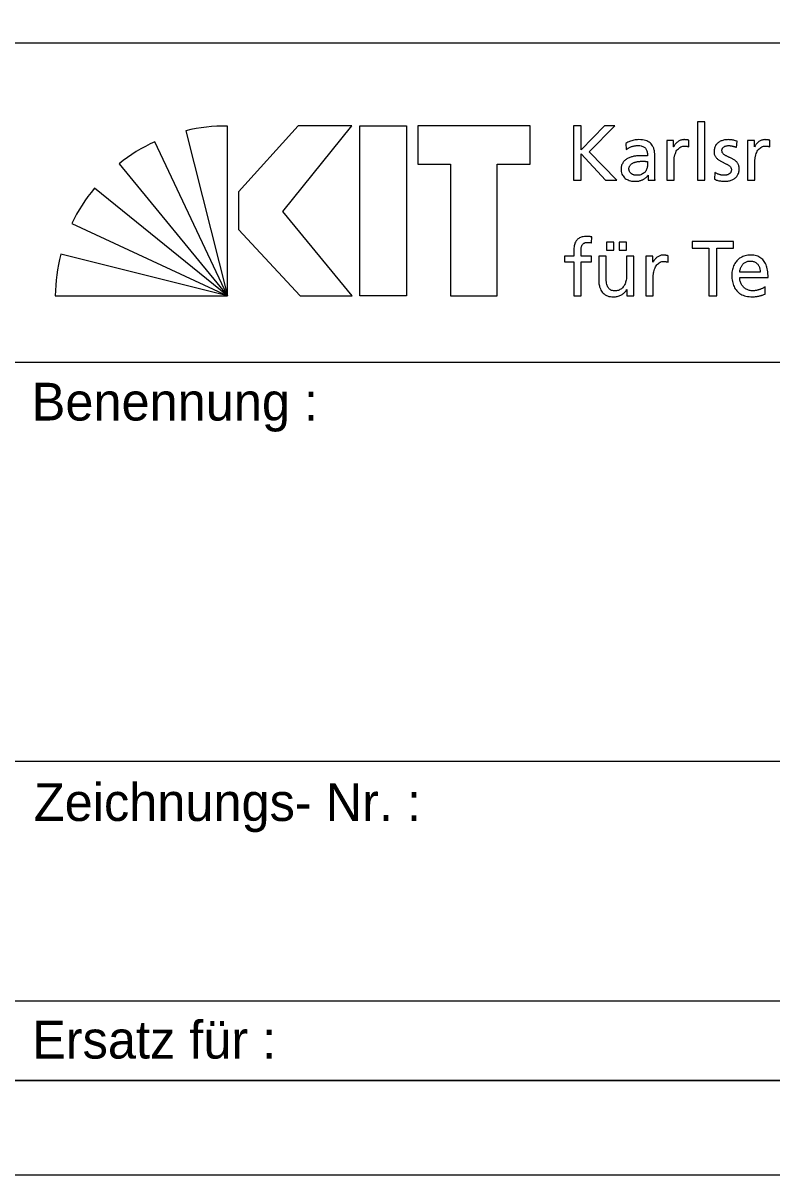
# Model space of a CAD drawing. Extents: x 0 to 297, y 0 to 210.
# Drawn here: x 252.83 to 272.66, y 0 to 30.52 of the extents above; entities that cross this region are included whole.
import ezdxf

# ---------------------------------------------------------------- set-up
doc = ezdxf.new("R2010")
doc.units = 0
doc.layers.add('90_Plankopf', color=7, linetype='Continuous')

msp = doc.modelspace()

# ---------------------------------------------------------------- linework, layer by layer
at = {"layer": '90_Plankopf'}
for p, q in [((205.56, 29.995), (294.5, 29.995)), ((205.56, 29.995), (294.5, 29.995)), ((258.24, 23.293), (258.24, 27.792)), ((267.405, 27.793), (267.405, 26.353)), ((257.137, 27.666), (258.24, 23.293)), ((258.24, 23.293), (256.317, 27.376)), ((268.79, 27.331), (268.8, 27.166)), ((270.463, 27.242), (270.463, 27.416)), ((271.728, 27.22), (271.745, 27.389)), ((272.606, 27.242), (272.606, 27.416)), ((269.559, 26.559), (269.559, 26.995)), ((255.372, 26.793), (258.24, 23.293)), ((269.365, 26.854), (269.365, 26.761)), ((271.149, 26.559), (271.138, 26.386)), ((267.405, 26.353), (267.611, 26.353)), ((268.253, 26.353), (268.554, 26.353)), ((258.24, 23.293), (254.717, 26.143)), ((254.12, 25.207), (258.24, 23.293)), ((267.887, 24.696), (267.895, 24.853)), ((258.24, 23.293), (253.829, 24.394)), ((269.913, 24.182), (269.913, 24.356)), ((272.353, 23.92), (271.808, 23.92)), ((271.808, 23.776), (272.559, 23.776)), ((272.479, 23.337), (272.479, 23.53)), ((253.682, 23.293), (258.24, 23.293)), ((252.501, 21.535), (294.5, 21.535)), ((252.501, 10.96), (294.5, 10.96)), ((252.501, 4.615), (294.5, 4.615)), ((294.5, 2.5), (205.56, 2.5)), ((211.4, 2.5), (294.5, 2.5)), ((211.4, 2.5), (294.5, 2.5))]:
    msp.add_line(p, q, dxfattribs=at)
for points in [[(0, 0), (297, 0), (297, 210), (0, 210)], [(12.5, 207.5), (294.5, 207.5), (294.5, 2.5), (12.5, 2.5)], [(261.533, 27.793), (260.118, 27.793), (258.536, 26.049), (258.536, 25.046), (260.169, 23.293), (261.542, 23.293), (259.711, 25.531)], [(262.985, 27.793), (262.985, 23.293), (261.751, 23.293), (261.751, 27.793)], [(263.281, 27.793), (263.281, 26.78), (264.151, 26.78), (264.151, 23.293), (265.385, 23.293), (265.385, 26.78), (266.255, 26.78), (266.255, 27.793)]]:
    msp.add_lwpolyline(points, close=True, dxfattribs=at)
for points in [[(268.554, 26.353), (267.824, 27.112), (268.5, 27.793), (268.226, 27.793), (267.611, 27.16), (267.611, 27.793), (267.405, 27.793)], [(270.69, 26.353), (270.884, 26.353), (270.884, 27.9), (270.69, 27.9), (270.69, 26.353)], [(270.061, 27.242), (270.057, 27.242), (270.057, 27.405), (269.875, 27.405), (269.875, 26.353), (270.069, 26.353), (270.069, 26.832)], [(272.203, 27.242), (272.199, 27.242), (272.199, 27.405), (272.018, 27.405), (272.018, 26.353), (272.212, 26.353), (272.212, 26.832)], [(267.611, 26.353), (267.611, 27.059), (268.253, 26.353)], [(269.382, 26.489), (269.386, 26.489), (269.386, 26.353), (269.567, 26.353)], [(270.995, 23.293), (271.201, 23.293), (271.201, 24.552), (271.649, 24.552), (271.649, 24.733), (270.547, 24.733), (270.547, 24.552), (270.995, 24.552), (270.995, 23.293)], [(267.412, 24.443), (267.412, 24.346), (267.165, 24.346), (267.165, 24.189), (267.412, 24.189), (267.412, 23.293), (267.606, 23.293), (267.606, 24.189), (267.885, 24.189), (267.885, 24.346), (267.606, 24.346), (267.606, 24.459)], [(268.277, 24.713), (268.277, 24.506), (268.471, 24.506), (268.471, 24.713), (268.277, 24.713)], [(268.615, 24.713), (268.615, 24.506), (268.809, 24.506), (268.809, 24.713), (268.615, 24.713)], [(268.271, 23.801), (268.271, 24.346), (268.077, 24.346), (268.077, 23.72)], [(269.007, 23.293), (269.007, 24.346), (268.813, 24.346), (268.813, 23.859)], [(269.511, 24.182), (269.507, 24.182), (269.507, 24.346), (269.325, 24.346), (269.325, 23.293), (269.519, 23.293), (269.519, 23.772)], [(268.816, 23.46), (268.82, 23.46), (268.82, 23.293), (269.007, 23.293)]]:
    msp.add_lwpolyline(points, dxfattribs=at)
for centre, start, end in [((258.224, 23.028), 89.8053, 103.1895), ((258.331, 23.059), 115.0126, 128.3968), ((258.408, 23.131), 140.7898, 154.174), ((258.446, 23.219), 165.7222, 179.1064)]:
    msp.add_arc(centre, 4.764, start, end, dxfattribs=at)
for points in [[(269.559, 26.995), (269.56, 27.09), (269.545, 27.17), (269.517, 27.235), (269.488, 27.3), (269.442, 27.348), (269.38, 27.381), (269.317, 27.413), (269.236, 27.43), (269.136, 27.43), (269.069, 27.43), (269.007, 27.42), (268.949, 27.402), (268.891, 27.384), (268.838, 27.361), (268.79, 27.331)], [(268.8, 27.166), (268.826, 27.188), (268.856, 27.207), (268.89, 27.223), (268.923, 27.239), (268.958, 27.251), (268.995, 27.26), (269.032, 27.269), (269.068, 27.273), (269.105, 27.273), (269.17, 27.273), (269.221, 27.263), (269.259, 27.243), (269.297, 27.222), (269.324, 27.191), (269.341, 27.151), (269.358, 27.11), (269.365, 27.059), (269.365, 26.999)], [(270.463, 27.416), (270.45, 27.418), (270.437, 27.421), (270.425, 27.423), (270.412, 27.425), (270.399, 27.427), (270.385, 27.428), (270.371, 27.429), (270.354, 27.43), (270.335, 27.43), (270.298, 27.43), (270.261, 27.422), (270.226, 27.406), (270.191, 27.39), (270.159, 27.368), (270.13, 27.339), (270.101, 27.311), (270.078, 27.279), (270.061, 27.242)], [(270.069, 26.832), (270.069, 26.92), (270.081, 26.996), (270.105, 27.06), (270.129, 27.124), (270.162, 27.174), (270.205, 27.208), (270.247, 27.243), (270.298, 27.26), (270.356, 27.261), (270.373, 27.261), (270.39, 27.26), (270.409, 27.257), (270.427, 27.254), (270.445, 27.249), (270.463, 27.242)], [(271.745, 27.389), (271.707, 27.4), (271.669, 27.41), (271.63, 27.418), (271.591, 27.426), (271.549, 27.43), (271.504, 27.43), (271.451, 27.43), (271.403, 27.423), (271.358, 27.41), (271.313, 27.397), (271.274, 27.377), (271.24, 27.35), (271.206, 27.323), (271.18, 27.29), (271.161, 27.249), (271.142, 27.208), (271.132, 27.161), (271.132, 27.106), (271.132, 27.064), (271.141, 27.028), (271.158, 26.997), (271.174, 26.966), (271.195, 26.94), (271.223, 26.917), (271.25, 26.895), (271.279, 26.875), (271.312, 26.857), (271.344, 26.84), (271.376, 26.824), (271.409, 26.809), (271.441, 26.793), (271.471, 26.777), (271.498, 26.761), (271.525, 26.745), (271.547, 26.727), (271.563, 26.706), (271.579, 26.686), (271.588, 26.663), (271.588, 26.636), (271.588, 26.607), (271.582, 26.584), (271.57, 26.564), (271.558, 26.545), (271.542, 26.529), (271.522, 26.518), (271.503, 26.506), (271.482, 26.498), (271.459, 26.493), (271.435, 26.487), (271.412, 26.485), (271.39, 26.485), (271.371, 26.485), (271.347, 26.488), (271.32, 26.493), (271.292, 26.499), (271.263, 26.507), (271.233, 26.518), (271.203, 26.529), (271.175, 26.543), (271.149, 26.559)], [(271.138, 26.386), (271.183, 26.363), (271.23, 26.347), (271.279, 26.339), (271.328, 26.331), (271.377, 26.327), (271.427, 26.328), (271.475, 26.328), (271.52, 26.335), (271.564, 26.348), (271.607, 26.361), (271.647, 26.381), (271.681, 26.408), (271.716, 26.435), (271.743, 26.469), (271.764, 26.51), (271.784, 26.551), (271.794, 26.6), (271.795, 26.656), (271.794, 26.704), (271.786, 26.745), (271.769, 26.778), (271.753, 26.811), (271.731, 26.84), (271.704, 26.863), (271.677, 26.886), (271.647, 26.906), (271.615, 26.922), (271.583, 26.939), (271.55, 26.954), (271.518, 26.968), (271.486, 26.983), (271.456, 26.998), (271.429, 27.013), (271.402, 27.029), (271.38, 27.047), (271.364, 27.068), (271.347, 27.089), (271.339, 27.115), (271.338, 27.145), (271.339, 27.174), (271.348, 27.198), (271.365, 27.217), (271.382, 27.236), (271.404, 27.25), (271.432, 27.259), (271.46, 27.269), (271.491, 27.273), (271.524, 27.273), (271.536, 27.273), (271.551, 27.271), (271.569, 27.269), (271.588, 27.266), (271.607, 27.261), (271.627, 27.256), (271.648, 27.251), (271.667, 27.246), (271.685, 27.239), (271.703, 27.233), (271.717, 27.226), (271.728, 27.22)], [(272.606, 27.416), (272.592, 27.418), (272.579, 27.421), (272.567, 27.423), (272.555, 27.425), (272.541, 27.427), (272.527, 27.428), (272.513, 27.429), (272.497, 27.43), (272.478, 27.43), (272.44, 27.43), (272.404, 27.422), (272.368, 27.406), (272.333, 27.39), (272.301, 27.368), (272.273, 27.339), (272.244, 27.311), (272.221, 27.279), (272.203, 27.242)], [(272.212, 26.832), (272.212, 26.92), (272.224, 26.996), (272.247, 27.06), (272.271, 27.124), (272.304, 27.174), (272.347, 27.208), (272.39, 27.243), (272.44, 27.26), (272.498, 27.261), (272.515, 27.261), (272.533, 27.26), (272.551, 27.257), (272.57, 27.254), (272.588, 27.249), (272.606, 27.242)], [(269.365, 26.999), (269.34, 27), (269.317, 27.001), (269.295, 27.001), (269.273, 27.002), (269.251, 27.003), (269.229, 27.003), (269.208, 27.003), (269.184, 27.003), (269.159, 27.003), (269.118, 27.003), (269.076, 26.999), (269.031, 26.992), (268.987, 26.985), (268.943, 26.973), (268.9, 26.957), (268.858, 26.941), (268.819, 26.919), (268.784, 26.892), (268.75, 26.866), (268.722, 26.833), (268.701, 26.794), (268.681, 26.755), (268.671, 26.709), (268.67, 26.656), (268.671, 26.58), (268.687, 26.518), (268.719, 26.469), (268.752, 26.421), (268.797, 26.385), (268.855, 26.362), (268.913, 26.339), (268.979, 26.328), (269.056, 26.328), (269.1, 26.328), (269.14, 26.334), (269.175, 26.344), (269.21, 26.355), (269.241, 26.368), (269.268, 26.384), (269.295, 26.401), (269.318, 26.419), (269.337, 26.437), (269.355, 26.455), (269.37, 26.472), (269.382, 26.489)], [(269.365, 26.761), (269.365, 26.709), (269.354, 26.661), (269.332, 26.62), (269.31, 26.578), (269.277, 26.546), (269.233, 26.522), (269.19, 26.498), (269.136, 26.485), (269.072, 26.485), (269.05, 26.485), (269.027, 26.489), (269.004, 26.496), (268.981, 26.503), (268.96, 26.514), (268.941, 26.529), (268.922, 26.543), (268.906, 26.561), (268.894, 26.582), (268.883, 26.604), (268.877, 26.628), (268.876, 26.656), (268.877, 26.693), (268.886, 26.724), (268.904, 26.749), (268.922, 26.773), (268.946, 26.793), (268.975, 26.807), (269.003, 26.822), (269.034, 26.833), (269.067, 26.841), (269.1, 26.848), (269.132, 26.853), (269.163, 26.855), (269.194, 26.858), (269.22, 26.859), (269.241, 26.858), (269.262, 26.858), (269.283, 26.858), (269.303, 26.856), (269.324, 26.855), (269.345, 26.855), (269.365, 26.854)], [(269.567, 26.353), (269.566, 26.363), (269.565, 26.377), (269.563, 26.393), (269.562, 26.411), (269.561, 26.433), (269.561, 26.46), (269.56, 26.486), (269.559, 26.52), (269.559, 26.559)], [(267.895, 24.853), (267.875, 24.856), (267.855, 24.859), (267.834, 24.862), (267.812, 24.864), (267.79, 24.866), (267.765, 24.866), (267.694, 24.865), (267.635, 24.855), (267.589, 24.836), (267.543, 24.816), (267.507, 24.787), (267.481, 24.75), (267.455, 24.713), (267.437, 24.668), (267.427, 24.616), (267.417, 24.565), (267.412, 24.507), (267.412, 24.443)], [(267.606, 24.459), (267.606, 24.495), (267.608, 24.528), (267.612, 24.558), (267.616, 24.588), (267.625, 24.615), (267.637, 24.637), (267.65, 24.66), (267.669, 24.677), (267.694, 24.69), (267.719, 24.702), (267.752, 24.709), (267.794, 24.709), (267.811, 24.709), (267.828, 24.708), (267.844, 24.706), (267.861, 24.703), (267.875, 24.7), (267.887, 24.696)], [(269.913, 24.356), (269.9, 24.359), (269.887, 24.361), (269.875, 24.363), (269.863, 24.365), (269.849, 24.367), (269.835, 24.368), (269.821, 24.37), (269.804, 24.37), (269.786, 24.37), (269.748, 24.37), (269.712, 24.362), (269.676, 24.346), (269.641, 24.33), (269.609, 24.308), (269.581, 24.28), (269.552, 24.252), (269.529, 24.219), (269.511, 24.182)], [(269.519, 23.772), (269.52, 23.86), (269.532, 23.937), (269.555, 24.001), (269.579, 24.065), (269.612, 24.114), (269.655, 24.148), (269.698, 24.183), (269.748, 24.201), (269.806, 24.201), (269.823, 24.201), (269.841, 24.2), (269.859, 24.197), (269.878, 24.195), (269.896, 24.19), (269.913, 24.182)], [(272.559, 23.776), (272.56, 23.861), (272.552, 23.94), (272.536, 24.012), (272.52, 24.084), (272.495, 24.146), (272.459, 24.2), (272.423, 24.254), (272.375, 24.295), (272.315, 24.325), (272.256, 24.355), (272.182, 24.37), (272.095, 24.37), (272.02, 24.37), (271.953, 24.357), (271.892, 24.331), (271.832, 24.305), (271.78, 24.269), (271.737, 24.221), (271.694, 24.174), (271.66, 24.118), (271.637, 24.052), (271.614, 23.988), (271.602, 23.916), (271.602, 23.838), (271.602, 23.752), (271.613, 23.674), (271.634, 23.604), (271.656, 23.535), (271.69, 23.475), (271.734, 23.425), (271.779, 23.375), (271.835, 23.336), (271.904, 23.309), (271.973, 23.282), (272.053, 23.269), (272.147, 23.268), (272.204, 23.269), (272.253, 23.273), (272.293, 23.28), (272.334, 23.288), (272.369, 23.297), (272.398, 23.307), (272.428, 23.317), (272.454, 23.327), (272.479, 23.337)], [(271.808, 23.92), (271.812, 23.955), (271.82, 23.989), (271.832, 24.024), (271.844, 24.058), (271.861, 24.089), (271.884, 24.118), (271.906, 24.147), (271.934, 24.17), (271.969, 24.187), (272.003, 24.204), (272.043, 24.213), (272.091, 24.213), (272.133, 24.213), (272.17, 24.206), (272.202, 24.19), (272.235, 24.175), (272.262, 24.154), (272.285, 24.127), (272.307, 24.101), (272.324, 24.069), (272.335, 24.034), (272.347, 23.999), (272.353, 23.961), (272.353, 23.92)], [(268.813, 23.859), (268.813, 23.794), (268.807, 23.736), (268.795, 23.683), (268.782, 23.63), (268.763, 23.584), (268.736, 23.546), (268.71, 23.507), (268.677, 23.478), (268.637, 23.457), (268.596, 23.436), (268.549, 23.426), (268.494, 23.425), (268.438, 23.429), (268.393, 23.444), (268.361, 23.473), (268.328, 23.501), (268.305, 23.542), (268.291, 23.597), (268.277, 23.651), (268.271, 23.719), (268.271, 23.801)], [(268.077, 23.72), (268.077, 23.626), (268.091, 23.545), (268.118, 23.478), (268.146, 23.41), (268.19, 23.359), (268.248, 23.323), (268.306, 23.287), (268.38, 23.269), (268.471, 23.268), (268.52, 23.269), (268.568, 23.276), (268.613, 23.291), (268.658, 23.307), (268.698, 23.329), (268.733, 23.357), (268.768, 23.386), (268.796, 23.42), (268.816, 23.46)], [(272.479, 23.53), (272.467, 23.521), (272.449, 23.51), (272.426, 23.497), (272.403, 23.485), (272.377, 23.474), (272.347, 23.463), (272.317, 23.452), (272.286, 23.443), (272.253, 23.436), (272.22, 23.429), (272.187, 23.426), (272.155, 23.425), (272.108, 23.426), (272.065, 23.434), (272.023, 23.451), (271.982, 23.468), (271.945, 23.492), (271.913, 23.523), (271.88, 23.554), (271.855, 23.59), (271.836, 23.633), (271.818, 23.676), (271.809, 23.724), (271.808, 23.776)]]:
    msp.add_open_spline(points, degree=3, dxfattribs=at)

# ---------------------------------------------------------------- texts
for s, p in [('Benennung :', (253.057, 19.989)), ('Zeichnungs- Nr. :', (253.114, 9.379)), ('Ersatz für :', (253.069, 3.084))]:
    msp.add_text(s, height=1, dxfattribs=at).set_placement(p)

doc.saveas('drawing.dxf')
